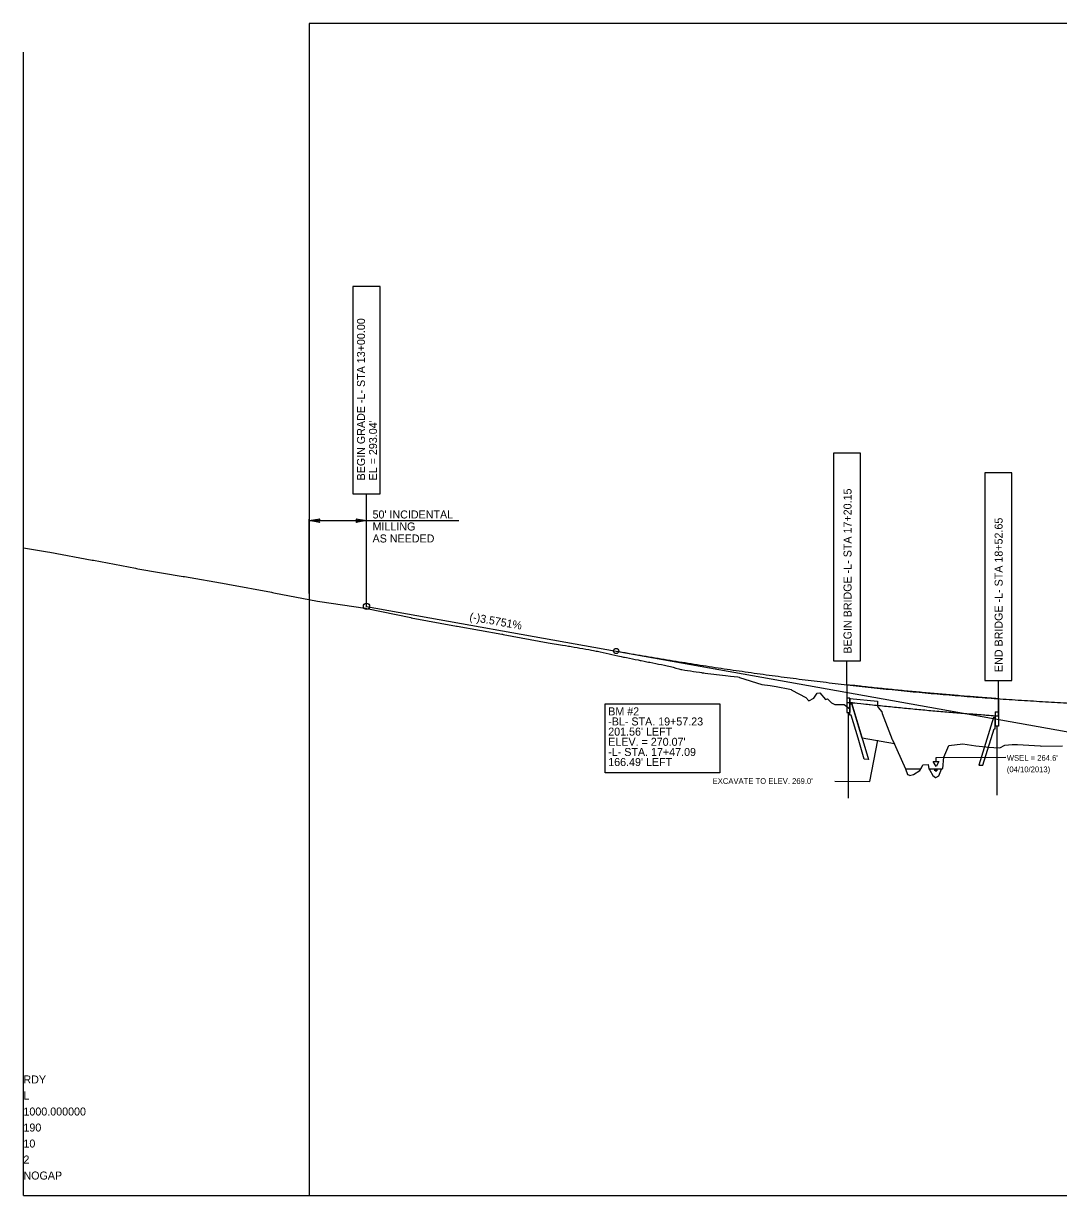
# Model space of a CAD drawing. Extents: x 10000 to 11818, y 10000 to 11025.
# Drawn here: x 10000 to 10905, y 10000 to 11025 of the extents above; entities that cross this region are included whole.
import ezdxf

# ---------------------------------------------------------------- set-up
doc = ezdxf.new("R2010")
doc.units = 0
for name, color, linetype in [('Default', 7, 'Continuous'), ('Exist Profile Cell', 7, 'Continuous'), ('Exist Vertical Profile Ground Line', 7, 'Continuous'), ('Old_Level_1', 7, 'Continuous'), ('Prop Grid Mask', 7, 'Continuous'), ('Prop Roadway Bridge', 7, 'Continuous'), ('Prop Shade Light', 7, 'Continuous'), ('Prop Terminator CELL', 7, 'Continuous'), ('Prop Vertical Profile Curve Label', 7, 'Continuous'), ('Prop Vertical Profile Grade', 7, 'Continuous'), ('Prop Vertical Profile Grade Label', 7, 'Continuous'), ('Prop VPI Label', 7, 'Continuous'), ('Sheet Layout Profile Border', 7, 'Continuous')]:
    doc.layers.add(name, color=color, linetype=linetype)

msp = doc.modelspace()

# ---------------------------------------------------------------- linework, layer by layer
at = {"layer": 'Default'}
for p, q in [((10722.8, 10435), (10720, 10435)), ((10720.1, 10435), (10720.1, 10422.5)), ((10722.8, 10435), (10722.8, 10422.5)), ((10720.1, 10422.5), (10722.8, 10422.5)), ((10721.3, 10422.5), (10721.3, 10347.5)), ((10849.8, 10423), (10849.8, 10410.5)), ((10849.8, 10423), (10852.6, 10423)), ((10852.6, 10423), (10852.6, 10410.5)), ((10852.6, 10414.4), (10852.6, 10411.4)), ((10852.6, 10410.5), (10849.8, 10410.5)), ((10851.3, 10410.5), (10851.3, 10350.1)), ((10795.5, 10373.1), (10800.5, 10373.1)), ((10796.5, 10372.1), (10799.5, 10372.1)), ((10797.5, 10371.1), (10798.5, 10371.1))]:
    msp.add_line(p, q, dxfattribs=at)
for points in [[(10722.8, 10430), (10724.4, 10430), (10739, 10381.4), (10735.3, 10381.5), (10729.9, 10400), (10723.8, 10420), (10722.8, 10420), (10722.8, 10422.5)], [(10849.8, 10418), (10848.2, 10418), (10835.6, 10376.3), (10839.1, 10376.4), (10848.8, 10408), (10849.8, 10408), (10849.8, 10410.5)], [(10795.6, 10379.5), (10800.6, 10379.5), (10798.1, 10375.1)]]:
    msp.add_lwpolyline(points, close=True, dxfattribs=at)
at = {"layer": 'Exist Profile Cell'}
for q in [(10000, 11000), (11817.5, 10000), (10000, 10000)]:
    msp.add_line((10000, 10000), q, dxfattribs=at)
at = {"layer": 'Exist Vertical Profile Ground Line'}
msp.add_line((10858.1, 10393.9), (10858.3, 10394), dxfattribs=at)
for points in [[(10000, 10566.3), (10019.2, 10563.2), (10021.1, 10563), (10023.1, 10562.6), (10060.1, 10555.7), (10061.4, 10555.5), (10098.1, 10548.5), (10099, 10548.3), (10099.9, 10548.1), (10139.8, 10541.5), (10140.9, 10541.3), (10177.2, 10534.8), (10178.8, 10534.6), (10216.8, 10527.6), (10217.8, 10527.4), (10218.9, 10527.2), (10257.3, 10519.7), (10259.3, 10519.4), (10298.8, 10513.6), (10299.8, 10513.4), (10300.4, 10513.3), (10338.8, 10505.4), (10339.2, 10505.3), (10378.7, 10498), (10379.1, 10498), (10379.4, 10497.9), (10418.5, 10490.9), (10419, 10490.8), (10419.4, 10490.7), (10451.1, 10484.9), (10458.8, 10483.4), (10471.5, 10481.3), (10474, 10480.9), (10476.6, 10480.5), (10477.4, 10480.3), (10479.1, 10480.1), (10481.7, 10479.6), (10484.2, 10479.2), (10486.7, 10478.7), (10489.3, 10478.3), (10491.8, 10477.9), (10494.4, 10477.4), (10496.9, 10477), (10498.5, 10476.7), (10499.6, 10476.5), (10500.9, 10476.2), (10502, 10476), (10504.5, 10475.4), (10507.1, 10474.8), (10509.6, 10474.2), (10512.2, 10473.7), (10514.7, 10473.1), (10517.3, 10472.5), (10519.8, 10471.9), (10522.6, 10471.3), (10524.9, 10470.9), (10525.5, 10470.8), (10527.4, 10470.4), (10530, 10469.9), (10532.5, 10469.4), (10535.1, 10468.9), (10537.6, 10468.4), (10539.3, 10468), (10540.1, 10467.8), (10542.7, 10467.3), (10545.2, 10466.8), (10546.7, 10466.5), (10547.8, 10466.3), (10550.3, 10465.8), (10552.9, 10465.3), (10555.4, 10464.8), (10557.9, 10464.3), (10560.5, 10463.8), (10563, 10463.3), (10565.8, 10462.7), (10568.1, 10462), (10570.6, 10461.3), (10573.2, 10460.5), (10574.8, 10460), (10575.7, 10459.9), (10578.3, 10459.5), (10580.8, 10459.1), (10583.4, 10458.8), (10585.9, 10458.4), (10588.4, 10458), (10591.2, 10457.6), (10593, 10457.3), (10593.5, 10457.2), (10594.9, 10457.1), (10596.1, 10456.9), (10598.6, 10456.6), (10601.2, 10456.3), (10603.7, 10456), (10606.2, 10455.7), (10608.8, 10455.4), (10611.3, 10455.1), (10613.9, 10454.8), (10618.4, 10454.3), (10624.8, 10453.5), (10625.8, 10453.2), (10626.2, 10453.1), (10645.7, 10446.9), (10652.9, 10446.1), (10658.4, 10445.1), (10670.3, 10442.7), (10671.3, 10442.4), (10671.9, 10441.9), (10684.2, 10435.4), (10686.9, 10432.7), (10691.1, 10435), (10694.1, 10439.2), (10696.6, 10439.5), (10701.4, 10433.7), (10703.3, 10434.5), (10706.8, 10430.9), (10709.6, 10429.5), (10717.6, 10429.5), (10721.2, 10426.9), (10722.9, 10425.4)], [(10746.9, 10427.9), (10747.6, 10426.7), (10750.6, 10423), (10751, 10421.5), (10759.6, 10398.8), (10760, 10398.5), (10771.5, 10373.2), (10773, 10368.2), (10774.9, 10367.7), (10775, 10367.3), (10778.3, 10368.3), (10783.9, 10371.8), (10785.3, 10373.9), (10786.6, 10376.6), (10791.2, 10376.9), (10791.7, 10373.2), (10792.8, 10371.9), (10795.2, 10367.4), (10797.5, 10365.5), (10798, 10365.6), (10800.5, 10367), (10802.8, 10372.9), (10804, 10373.4), (10804.8, 10383.3), (10809.4, 10393.6)], [(10809.4, 10393.6), (10821.4, 10394.9), (10833, 10393.4), (10841.7, 10392.3), (10843, 10392.2)], [(10843.3, 10392.2), (10854, 10391.6), (10858.1, 10393.9)], [(10858.3, 10394), (10864.8, 10394.4), (10869.3, 10394.5), (10889, 10393.2), (10889.9, 10393.1), (10908.7, 10393.2)]]:
    msp.add_lwpolyline(points, dxfattribs=at)
at = {"layer": 'Old_Level_1'}
msp.add_lwpolyline([(10722.8, 10434.8), (10746.9, 10432.2), (10746.9, 10427.9), (10747.6, 10426.7), (10750.6, 10423), (10751, 10421.5), (10759.6, 10398.8), (10760, 10398.5), (10761.7, 10394.9), (10733.4, 10399.9), (10724.4, 10430), (10722.8, 10430), (10722.8, 10433.9)], close=True, dxfattribs=at)
at = {"layer": 'Prop Grid Mask'}
for points in [[(10288.1, 10613.6), (10311.9, 10613.6), (10311.9, 10795.1), (10288.1, 10795.1)], [(10708.3, 10467.7), (10732, 10467.7), (10732, 10649.2), (10708.3, 10649.2)], [(10840.8, 10450.4), (10864.5, 10450.4), (10864.5, 10631.9), (10840.8, 10631.9)], [(10508.8, 10430), (10609, 10430), (10609, 10369.6), (10508.8, 10369.6)]]:
    msp.add_lwpolyline(points, close=True, dxfattribs=at)
at = {"layer": 'Prop Roadway Bridge'}
for p, q in [((10720.2, 10446.4), (10720.2, 10426.3)), ((10852.6, 10434.4), (10852.6, 10414.4))]:
    msp.add_line(p, q, dxfattribs=at)
at = {"layer": 'Prop Shade Light'}
for p, q in [((10720.2, 10446.7), (10720.2, 10431.3)), ((10852.6, 10419.4), (10852.6, 10434.5))]:
    msp.add_line(p, q, dxfattribs=at)
for points in [[(10852.6, 10434.5), (10846.3, 10434.9), (10839.8, 10435.4), (10833.3, 10435.9), (10826.3, 10436.4), (10819.3, 10437), (10812.3, 10437.6), (10805.3, 10438.2), (10798.3, 10438.8), (10791.3, 10439.4), (10784.3, 10440.1), (10777.3, 10440.7), (10770.3, 10441.4), (10763.3, 10442.1), (10756.3, 10442.8), (10749.3, 10443.5), (10742.3, 10444.2), (10735.3, 10445), (10728.3, 10445.8), (10728.1, 10445.8), (10728, 10445.8), (10720.2, 10446.7)], [(10720.2, 10431.3), (10734.5, 10430), (10741.1, 10429.3), (10747.7, 10428.6), (10754.8, 10427.9), (10761.8, 10427.2), (10768.8, 10426.5), (10775.9, 10425.8), (10782.9, 10425.1), (10789.9, 10424.5), (10797, 10423.8), (10804, 10423.2), (10811, 10422.6), (10818.1, 10422.1), (10825.1, 10421.5), (10832.1, 10421), (10839, 10420.4), (10845.9, 10419.9), (10852.6, 10419.4)]]:
    msp.add_open_spline(points, degree=3, dxfattribs=at)
at = {"layer": 'Prop Terminator CELL'}
for points in [[(10259, 10588.6), (10250, 10590.2), (10259.1, 10591.8), (10257.9, 10590.2)], [(10291, 10591.7), (10300, 10590.2), (10291, 10588.6), (10292.1, 10590.2)]]:
    msp.add_lwpolyline(points, close=True, dxfattribs=at)
at = {"layer": 'Prop Vertical Profile Curve Label'}
msp.add_circle((10518.3, 10476.2), 2.25, dxfattribs=at)
at = {"layer": 'Prop Vertical Profile Grade'}
for p, q in [((10300, 10515.2), (10518.3, 10476.2)), ((10720.2, 10446.7), (10720.2, 10431.6)), ((10852.6, 10434.5), (10852.6, 10419.4))]:
    msp.add_line(p, q, dxfattribs=at)
msp.add_spline([(10518.3, 10476.2), (10539.3, 10472.5), (10560.3, 10469), (10581.3, 10465.6), (10602.3, 10462.3), (10623.3, 10459.2), (10644.3, 10456.2), (10665.3, 10453.4), (10686.3, 10450.7), (10707.3, 10448.2), (10728.3, 10445.8), (10749.3, 10443.5), (10770.3, 10441.4), (10791.3, 10439.4), (10812.3, 10437.6), (10833.3, 10435.9), (10854.3, 10434.4), (10875.3, 10433), (10896.3, 10431.7), (10917.3, 10430.6), (10938.3, 10429.6), (10959.3, 10428.8), (10980.3, 10428.1), (11001.3, 10427.5), (11022.3, 10427.1), (11043.3, 10426.9), (11064.3, 10426.8), (11085.3, 10426.8), (11106.3, 10426.9), (11127.3, 10427.3), (11148.3, 10427.7), (11169.3, 10428.3), (11190.3, 10429), (11211.3, 10429.9), (11232.3, 10430.9), (11253.3, 10432.1), (11274.3, 10433.4), (11295.3, 10434.9), (11316.3, 10436.4), (11337.3, 10438.2), (11358.3, 10440.1), (11379.3, 10442.1), (11400.3, 10444.2), (11421.3, 10446.5), (11442.3, 10449), (11463.3, 10451.6), (11484.3, 10454.3), (11505.3, 10457.2), (11526.3, 10460.2), (11547.3, 10463.4), (11568.3, 10466.7)], degree=3, dxfattribs=at)
msp.add_open_spline([(10720.2, 10431.6), (10734.5, 10430), (10741.1, 10429.3), (10747.7, 10428.6), (10754.8, 10427.9), (10761.8, 10427.2), (10768.8, 10426.5), (10775.9, 10425.8), (10782.9, 10425.1), (10789.9, 10424.5), (10797, 10423.8), (10804, 10423.2), (10811, 10422.6), (10818.1, 10422.1), (10825.1, 10421.5), (10832.1, 10421), (10839, 10420.4), (10845.8, 10419.9), (10852.6, 10419.4)], degree=3, dxfattribs=at)
at = {"layer": 'Prop VPI Label'}
for p, q in [((10300, 10514.6), (10300, 10613.6)), ((10250, 10526.6), (10250, 10591.5)), ((10250, 10590.2), (10300, 10590.2)), ((10300, 10590.2), (10380.8, 10590.2)), ((10518.3, 10476.2), (11040.6, 10382.8)), ((10720.2, 10446.7), (10720.2, 10467.7)), ((10852.6, 10434.5), (10852.6, 10450.4)), ((10771.7, 10373.1), (10784.8, 10373.1)), ((10791.8, 10373.1), (10803.4, 10373.1))]:
    msp.add_line(p, q, dxfattribs=at)
for points in [[(10709.7, 10362.3), (10740.1, 10362.2), (10747.3, 10398.1)], [(10859, 10383), (10798, 10382.9), (10798, 10379)]]:
    msp.add_lwpolyline(points, dxfattribs=at)
msp.add_circle((10300, 10515.2), 2.75, dxfattribs=at)
at = {"layer": 'Sheet Layout Profile Border'}
msp.add_lwpolyline([(10250, 11025), (10250, 10000), (10250, 10000), (11635, 10000), (11635, 10000), (11635, 10887.5), (11635, 10887.5), (11492.5, 10887.5), (11492.5, 11025)], close=True, dxfattribs=at)

# ---------------------------------------------------------------- texts
at = {"layer": 'Exist Profile Cell'}
for s, p in [('RDY', (10000, 10098)), ('L', (10000, 10084)), ('1000.000000', (10000, 10070)), ('190', (10000, 10056)), ('10', (10000, 10042)), ('2', (10000, 10028)), ('NOGAP', (10000, 10014))]:
    msp.add_text(s, height=7, dxfattribs=at).set_placement(p)
at = {"layer": 'Prop Vertical Profile Grade Label'}
msp.add_text('(-)3.5751%', height=7, rotation=349.8652, dxfattribs=at).set_placement((10389.7, 10503))
at = {"layer": 'Prop VPI Label'}
for s, height, rotation, p in [('BEGIN GRADE -L- STA 13+00.00', 7, 90, (10298.7, 10625.4)), ("EL = 293.04'", 7, 90, (10309.2, 10625.4)), ('BEGIN BRIDGE -L- STA 17+20.15 ', 7, 90, (10724.2, 10473.9)), ("50' INCIDENTAL", 7, 360, (10305.3, 10592.1)), ('MILLING', 7, 360, (10305.3, 10581.6)), ('END BRIDGE -L- STA 18+52.65', 7, 90, (10856.3, 10457.8)), ('AS NEEDED', 7, 360, (10305.3, 10571.1)), ("WSEL = 264.6'", 5, 0.0084, (10860, 10380.2)), ('(04/10/2013)', 5, 0.0084, (10860, 10370.2)), ("EXCAVATE TO ELEV. 269.0'", 5, 0.0084, (10602.7, 10360))]:
    msp.add_text(s, height=height, rotation=rotation, dxfattribs=at).set_placement(p)
for s, p in [('BM #2', (10511.4, 10419.9)), ('-BL- STA. 19+57.23', (10511.4, 10411.1)), ("201.56' LEFT", (10511.4, 10402.2)), ("ELEV. = 270.07'", (10511.4, 10393.3)), ('-L- STA. 17+47.09', (10511.4, 10384.4)), ("166.49' LEFT", (10511.4, 10375.6))]:
    msp.add_text(s, height=7, dxfattribs=at).set_placement(p)

doc.saveas('drawing.dxf')
